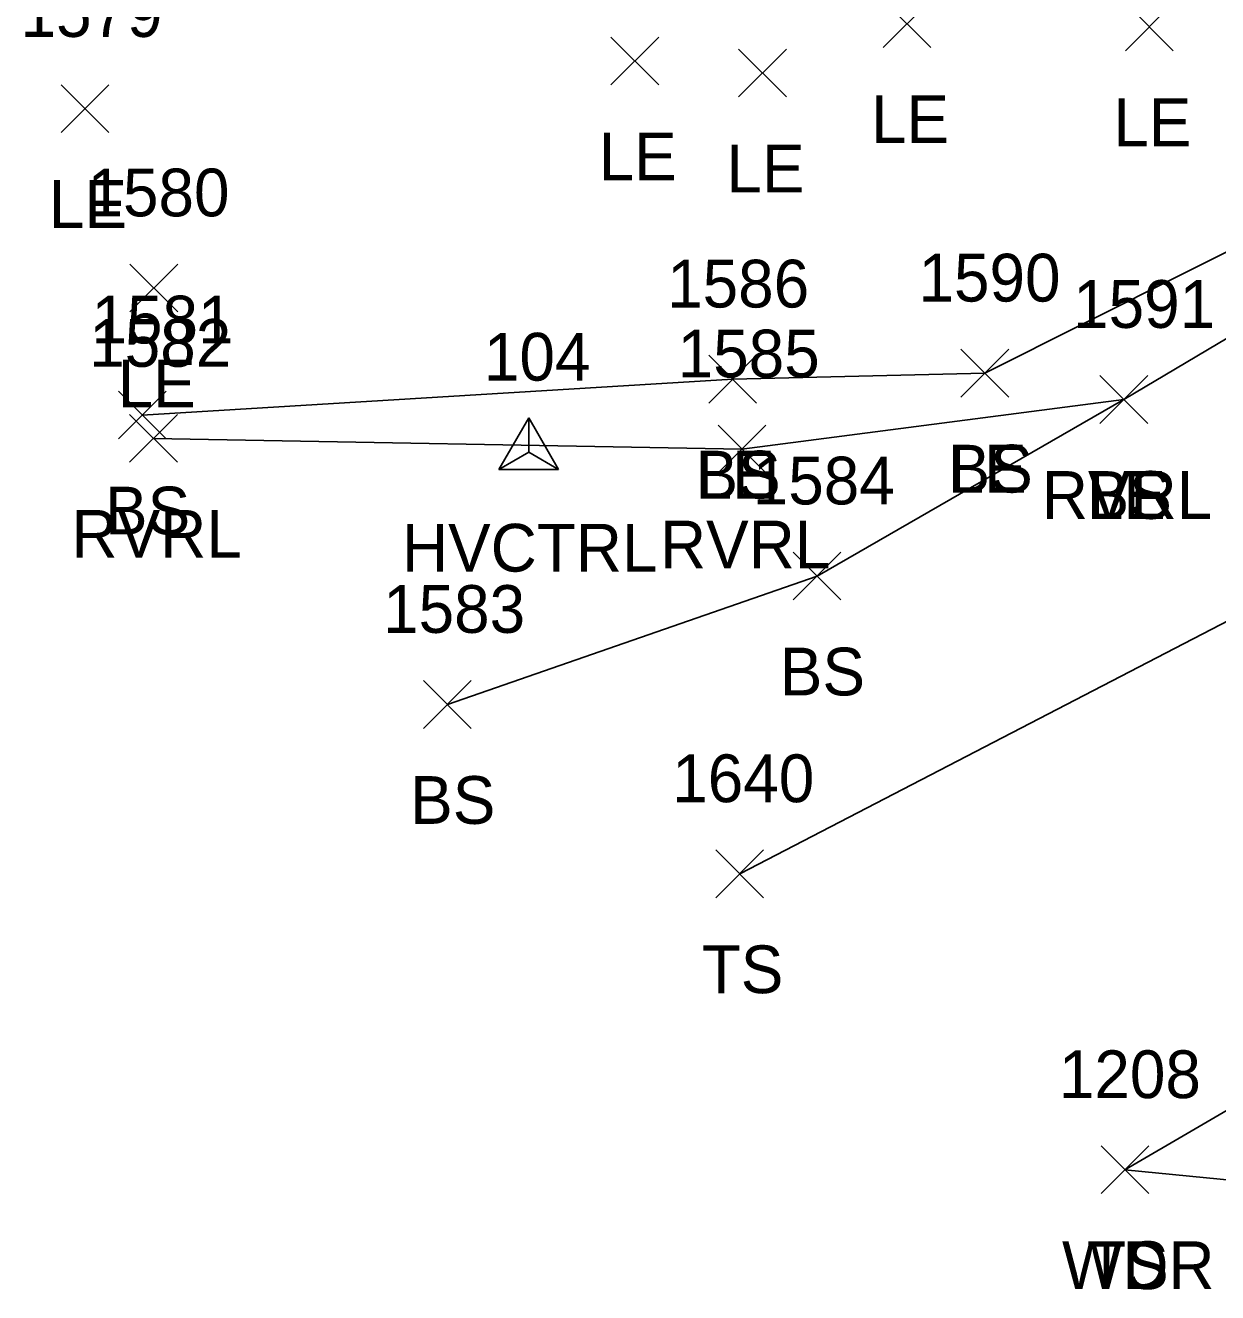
# Model space of a CAD drawing. Extents: x 1620157 to 1620595, y 115111 to 117885.
# Drawn here: x 1620225.8 to 1620275.8, y 115305.5 to 115358.6 of the extents above; entities that cross this region are included whole.
import ezdxf

# ---------------------------------------------------------------- set-up
doc = ezdxf.new("R2010")
doc.units = 0
for name, color, linetype in [('C_A', 7, 'Continuous'), ('C_I', 7, 'Continuous'), ('CPSM', 7, 'Continuous'), ('L_A', 7, 'Continuous'), ('L_I', 7, 'Continuous'), ('L_TIC', 7, 'Continuous'), ('LAWA', 7, 'Continuous'), ('LAWE', 7, 'Continuous'), ('LELB', 7, 'Continuous')]:
    doc.layers.add(name, color=color, linetype=linetype)

msp = doc.modelspace()

# ---------------------------------------------------------------- linework, layer by layer
at = {"layer": 'CPSM'}
for p, q in [((1620245.651, 115339.979), (1620246.901, 115342.145)), ((1620248.151, 115339.979), (1620246.901, 115342.145)), ((1620246.901, 115340.701), (1620246.901, 115342.145)), ((1620245.651, 115339.979), (1620246.901, 115340.701)), ((1620246.901, 115340.701), (1620246.901, 115340.701)), ((1620246.901, 115340.701), (1620248.151, 115339.979)), ((1620245.651, 115339.979), (1620248.151, 115339.979))]:
    msp.add_line(p, q, dxfattribs=at)
at = {"layer": 'L_TIC'}
for points in [[(1620261.746, 115357.654), (1620263.746, 115359.654)], [(1620263.746, 115357.654), (1620261.746, 115359.654)], [(1620271.896, 115357.518), (1620273.896, 115359.518)], [(1620273.896, 115357.518), (1620271.896, 115359.518)], [(1620250.345, 115356.087), (1620252.345, 115358.087)], [(1620252.345, 115356.087), (1620250.345, 115358.087)], [(1620255.692, 115355.582), (1620257.692, 115357.582)], [(1620257.692, 115355.582), (1620255.692, 115357.582)], [(1620227.319, 115354.097), (1620229.319, 115356.097)], [(1620229.319, 115354.097), (1620227.319, 115356.097)], [(1620230.202, 115346.581), (1620232.202, 115348.581)], [(1620232.202, 115346.581), (1620230.202, 115348.581)], [(1620254.446, 115342.763), (1620256.446, 115344.763)], [(1620256.446, 115342.763), (1620254.446, 115344.763)], [(1620254.446, 115342.763), (1620256.446, 115344.763)], [(1620256.446, 115342.763), (1620254.446, 115344.763)], [(1620265.003, 115343.013), (1620267.003, 115345.013)], [(1620267.003, 115343.013), (1620265.003, 115345.013)], [(1620265.003, 115343.013), (1620267.003, 115345.013)], [(1620267.003, 115343.013), (1620265.003, 115345.013)], [(1620270.825, 115341.909), (1620272.825, 115343.909)], [(1620272.825, 115341.909), (1620270.825, 115343.909)], [(1620270.825, 115341.909), (1620272.825, 115343.909)], [(1620272.825, 115341.909), (1620270.825, 115343.909)], [(1620270.825, 115341.909), (1620272.825, 115343.909)], [(1620272.825, 115341.909), (1620270.825, 115343.909)], [(1620229.717, 115341.258), (1620231.717, 115343.258)], [(1620231.717, 115341.258), (1620229.717, 115343.258)], [(1620230.187, 115340.28), (1620232.187, 115342.28)], [(1620232.187, 115340.28), (1620230.187, 115342.28)], [(1620254.832, 115339.835), (1620256.832, 115341.835)], [(1620256.832, 115339.835), (1620254.832, 115341.835)], [(1620257.976, 115334.515), (1620259.976, 115336.515)], [(1620259.976, 115334.515), (1620257.976, 115336.515)], [(1620242.496, 115329.135), (1620244.496, 115331.135)], [(1620244.496, 115329.135), (1620242.496, 115331.135)], [(1620254.739, 115322.043), (1620256.739, 115324.043)], [(1620256.739, 115322.043), (1620254.739, 115324.043)], [(1620270.873, 115309.647), (1620272.873, 115311.647)], [(1620272.873, 115309.647), (1620270.873, 115311.647)], [(1620270.873, 115309.647), (1620272.873, 115311.647)], [(1620272.873, 115309.647), (1620270.873, 115311.647)]]:
    msp.add_lwpolyline(points, dxfattribs=at)
at = {"layer": 'LAWA'}
msp.add_lwpolyline([(1620292.544, 115308.613), (1620271.873, 115310.647)], dxfattribs=at)
at = {"layer": 'LAWE'}
msp.add_lwpolyline([(1620231.187, 115341.28), (1620255.832, 115340.835), (1620271.825, 115342.909), (1620282.718, 115349.37), (1620290.514, 115351.088), (1620308.474, 115349.924), (1620319.423, 115355.785), (1620323.167, 115359.94), (1620321.602, 115374.201), (1620322.123, 115377.536), (1620326.931, 115387.408)], dxfattribs=at)
at = {"layer": 'LELB'}
for points in [[(1620230.717, 115342.258), (1620255.446, 115343.763), (1620266.003, 115344.013), (1620278.661, 115350.372), (1620291.124, 115352.303), (1620304.673, 115357.818), (1620320.504, 115370.294)], [(1620332.004, 115369.254), (1620327.77, 115368.93), (1620326.291, 115361.539), (1620331.798, 115352.573), (1620335.893, 115347.526), (1620330.791, 115343.259), (1620318.913, 115350.016), (1620306.405, 115344.415), (1620294.346, 115343.273), (1620287.578, 115341.357), (1620278.524, 115334.856), (1620255.739, 115323.043)], [(1620343.048, 115305.499), (1620344.059, 115317.867), (1620344.086, 115333.817), (1620341.166, 115344.372), (1620338.827, 115343.311), (1620331.839, 115338.897), (1620319.572, 115325.443), (1620307.11, 115319.051), (1620298.273, 115319.141), (1620283.642, 115317.517), (1620271.873, 115310.647)], [(1620243.496, 115330.135), (1620258.976, 115335.515), (1620271.825, 115342.909)]]:
    msp.add_lwpolyline(points, dxfattribs=at)

# ---------------------------------------------------------------- texts
at = {"layer": 'C_A'}
msp.add_text('HVCTRL', height=2, dxfattribs=at).set_placement((1620241.594, 115335.701))
at = {"layer": 'C_I'}
msp.add_text('104', height=2, dxfattribs=at).set_placement((1620245.027, 115343.701))
at = {"layer": 'L_A'}
for s, p in [('LE', (1620261.235, 115353.654)), ('LE', (1620271.384, 115353.518)), ('LE', (1620249.833, 115352.087)), ('LE', (1620255.181, 115351.582)), ('LE', (1620226.807, 115350.097)), ('LE', (1620229.69, 115342.581)), ('BS', (1620264.444, 115339.013)), ('LE', (1620264.491, 115339.013)), ('BS', (1620253.887, 115338.763)), ('LE', (1620253.934, 115338.763)), ('RVRL', (1620268.392, 115337.909)), ('BS', (1620270.266, 115337.909)), ('LE', (1620270.314, 115337.909)), ('BS', (1620229.157, 115337.258)), ('RVRL', (1620227.754, 115336.28)), ('RVRL', (1620252.399, 115335.835)), ('BS', (1620257.417, 115330.515)), ('BS', (1620241.937, 115325.135)), ('TS', (1620254.148, 115318.043)), ('WDR', (1620269.236, 115305.647)), ('TS', (1620270.283, 115305.647))]:
    msp.add_text(s, height=2, dxfattribs=at).set_placement(p)
at = {"layer": 'L_I'}
for s, p in [('1579', (1620225.618, 115358.097)), ('1580', (1620228.422, 115350.581)), ('1590', (1620263.223, 115347.013)), ('1590', (1620263.223, 115347.013)), ('1586', (1620252.698, 115346.763)), ('1586', (1620252.698, 115346.763)), ('1591', (1620269.699, 115345.909)), ('1591', (1620269.699, 115345.909)), ('1591', (1620269.699, 115345.909)), ('1581', (1620228.591, 115345.258)), ('1582', (1620228.495, 115344.28)), ('1585', (1620253.139, 115343.835)), ('1584', (1620256.283, 115338.515)), ('1583', (1620240.803, 115333.135)), ('1640', (1620252.912, 115326.043)), ('1208', (1620269.102, 115313.647)), ('1208', (1620269.102, 115313.647))]:
    msp.add_text(s, height=2, dxfattribs=at).set_placement(p)

doc.saveas('drawing.dxf')
